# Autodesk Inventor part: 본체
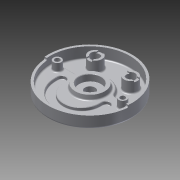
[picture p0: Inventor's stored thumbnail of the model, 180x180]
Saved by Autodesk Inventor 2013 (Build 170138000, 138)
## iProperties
Created: 2015-05
Part Number: 본체
Material: 알루미늄 6061
Document SubType Name: Modeling
Designer: Administrator
Density: 2.71 g/cm^3
Mass: 1085.43 g
Surface Area: 1039.14 cm^2
Volume: 400.527 cm^3
Author: Administrator
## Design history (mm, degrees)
sketch "스케치1"
  geometry: C1 r 95 at (0, 0); 1 further point
  constraints: 1 centre point, 1 coincident
  dimensions: "d0" = 190 diameter of C1
extrude "돌출1" new body sketch "스케치1" distance "d2" = 32; taper "d3" = 0 deg
sketch "스케치2"
  geometry: C1 r 95 at (0, 0) reference; C2 r 90 at (0, 0)
  constraints: 1 centre point, 1 coincident
  dimensions: "d4" = 180 diameter of C2
extrude "돌출2" cut sketch "스케치2" distance "d6" = 18; taper "d7" = 0 deg
sketch "스케치3"
  geometry: L1 (-89.196, 12)-(89.196, 12); L2 (-82.153, -19)-(80.893, -19); L3 (0, 0)-(0, -95); L4 (-82.153, -14)-(80.893, -14); L5 (59, -19)-(59, -14); L6 (41, -19)-(41, -14); L7 (-41, -19)-(-41, -14); L8 (-59, -19)-(-59, -14); A1 r 90 centre (0, 0) between (89.196, 12) and (-89.196, 12); A2 r 59 centre (0, -19) between (-59, -19) and (59, -19); A3 r 41 centre (0, -19) between (-41, -19) and (41, -19); A4 r 9 centre (50, -14) between (59, -14) and (41, -14); A5 r 9 centre (-50, -14) between (-41, -14) and (-59, -14); 3 further points
  constraints: 16 end point, 10 point on circle, 5 centre point, 5 point on line, 3 parallel, 3 symmetric about line, 3 tangent, 2 coincident, 2 perpendicular, 1 horizontal, 1 horizontal alignment, 1 midpoint, 1 vertical alignment, 2 other
  dimensions: "d10" = 90 radius of A1; "d11" = 12 distance from line of L1 point (0, 0); "d13" = 59 radius of A2; "d14" = 41 radius of A3; "d16" = 18 diameter of A4; "d17" = 5 distance of L8.start L8.end; "d18" = 5 distance of L7.start L7.end; "d130" = 19 distance from line of L2 L3.start; "d131" = 5 distance between parallel lines of L4 L2
extrude "돌출3" cut sketch "스케치3" distance "d19" = 7; taper "d20" = 0 deg
sketch "스케치4"
  geometry: L1 (89.196, 12)-(-89.196, 12) reference; A1 r 90 centre (0, 0) between (89.196, 12) and (-89.196, 12) reference; A2 r 42 centre (0, 0) between (40.249, 12) and (-40.249, 12)
  constraints: 2 point on circle, 2 point on line, 1 centre point, 1 coincident
  dimensions: "d21" = 84 diameter of A2
extrude "돌출4" join sketch "스케치4" distance "d23" = 7; taper "d24" = 0 deg
sketch "스케치5"
  geometry: C1 r 35 at (0, 0); A1 r 90 centre (0, 0) between (-89.196, 12) and (89.196, 12) reference
  constraints: 1 centre point, 1 coincident
  dimensions: "d25" = 70 diameter of C1
extrude "돌출5" join sketch "스케치5" distance "d26" = 10; taper "d27" = -10 deg
sketch "스케치6"
  geometry: C1 r 95 at (0, 0) reference; C2 r 25 at (0, 0)
  constraints: 1 centre point, 1 coincident
  dimensions: "d28" = 50 diameter of C2
extrude "돌출6" join sketch "스케치6" distance "d29" = 12; taper "d30" = -15 deg
hole "구멍1" diameter "d33" = 23; stored, may be unused: countersink angle "d37" = 90 deg, drill point angle "d39" = 0 deg; dims "d34" = 6, "d35" = 50, "d36" = 15, "d38" = 15, "d132" = 10, "d133" = 10
sketch "스케치7"
  geometry: L1 (-40.249, 12)-(-89.196, 12) reference; L2 (0, 90)-(0, 0); C1 r 15 at (-40, 52); C2 r 15 at (40, 52); A1 r 42 centre (0, 0) between (40.249, 12) and (-40.249, 12) reference; A2 r 90 centre (0, 0) between (89.196, 12) and (-89.196, 12) reference
  constraints: 2 centre point, 2 end point, 1 perpendicular, 1 point on circle, 1 symmetric about line, 1 other
  dimensions: "d42" = 30 diameter of C1; "d43" = 80 distance of C2.centre C1.centre; "d44" = 52 vertical distance of C2.centre A1.centre
extrude "돌출7" join sketch "스케치7" distance "d45" = 25; taper "d46" = 0 deg
hole "구멍2" diameter "d49" = 20; stored, may be unused: countersink angle "d53" = 90 deg, drill point angle "d55" = 0 deg; dims "d47" = 10, "d48" = 10, "d50" = 6, "d51" = 4, "d52" = 2, "d54" = 15
hole "구멍3" diameter "d58" = 20; stored, may be unused: countersink angle "d62" = 90 deg, drill point angle "d64" = 0 deg; dims "d56" = 10, "d57" = 10, "d59" = 6, "d60" = 4, "d61" = 2, "d63" = 15
sketch "스케치8"
  geometry: L1 (-6, 17.94)-(6, 17.94); L2 (6, 17.94)-(6, -17.94); L3 (6, -17.94)-(-6, -17.94); L4 (-6, -17.94)-(-6, 17.94); C1 r 10 at (0, 0) reference; 3 further points
  constraints: 8 end point, 2 midpoint, 2 parallel, 1 horizontal, 1 horizontal alignment, 1 perpendicular, 1 vertical alignment
  dimensions: "d65" = 12 distance between parallel lines of L2 L4; "d67" = 35.87996 distance between parallel lines of L3 L1
extrude "돌출8" cut sketch "스케치8" distance "d68" = 3; taper "d69" = 0 deg
sketch "스케치9"
  geometry: L1 (-18.483, 6)-(18.483, 6); L2 (18.483, 6)-(18.483, -6); L3 (18.483, -6)-(-18.483, -6); L4 (-18.483, -6)-(-18.483, 6); C1 r 10 at (0, 0) reference; 3 further points
  constraints: 8 end point, 2 midpoint, 2 parallel, 1 horizontal, 1 horizontal alignment, 1 perpendicular, 1 vertical alignment
  dimensions: "d70" = 12 distance between parallel lines of L3 L1; "d72" = 36.96686 distance between parallel lines of L2 L4
extrude "돌출9" cut sketch "스케치9" distance "d73" = 3; taper "d74" = 0 deg
sketch "스케치10"
  geometry: L1 (0, 0)-(0, -90); C1 r 35 at (0, 0) reference; C2 r 95 at (0, 0) reference; C3 r 9 at (-74, 0); C4 r 9 at (74, 0); A1 r 90 centre (0, 0) between (-89.196, 12) and (89.196, 12) reference
  constraints: 2 centre point, 2 end point, 1 horizontal alignment, 1 point on circle, 1 symmetric about line, 1 other
  dimensions: "d75" = 18 diameter of C3; "d76" = 148 distance of C4.centre C3.centre
extrude "돌출10" join sketch "스케치10" distance "d77" = 18; taper "d78" = 0 deg
sketch "스케치11"
  geometry: C1 r 9 at (-74, 0) reference; C2 r 9 at (74, 0) reference; C3 r 9 at (-74, 0) reference; 2 further points
  constraints: 2 coincident
hole "구멍4" sketch "스케치11" at (-74, 0), (74, 0) diameter "d79" = 11; stored, may be unused: countersink angle "d83" = 90 deg, drill point angle "d85" = 0 deg; dims "d80" = 6, "d81" = 18, "d82" = 11, "d84" = 15
sketch "스케치12"
  geometry: L1 (0, 0)-(-89.658, -7.844); L2 (0, 0)-(89.658, -7.844); L3 (-90, 0)-(90, 0); L4 (89.658, -7.844)-(94.638, -8.28); L5 (-89.658, -7.844)-(-94.638, -8.28); A1 r 90 centre (0, 0) between (-90, 0) and (89.196, 12) reference; A2 r 95 centre (0, 0) between (-94.638, -8.28) and (94.638, -8.28) reference; A3 r 90 centre (0, 0) between (-89.196, 12) and (89.196, 12) reference; A4 r 95 centre (0, 0) between (-94.638, -8.28) and (94.638, -8.28); A5 r 90 centre (0, 0) between (89.658, -7.844) and (-89.658, -7.844)
  constraints: 10 end point, 9 point on circle, 2 centre point, 2 coincident, 1 concentric, 1 horizontal, 1 midpoint
  dimensions: "d86" = 180 diameter of A5; "d88" = 5 deg angle of L1 L3; "d90" = 5 deg angle of L2 L3; "d92" = 5 deg angle of L5 L3; "d94" = 5 deg angle of L4 L3
extrude "돌출11" cut sketch "스케치12" distance "d96" = 5; taper "d97" = 0 deg
fillet "모깎기1" dims "d98" = 10
sketch "스케치13"
  geometry: L1 (0, 0)-(0, -72); L2 (0, 0)-(-36.062, -36.062); L3 (0, 0)-(36.062, -36.062); L4 (-36.062, -36.062)-(-50.912, -50.912); L5 (36.062, -36.062)-(50.912, -50.912); C1 r 25 at (0, 0) reference; C2 r 11.5 at (0, 0) reference; A1 r 51 centre (0, 0) between (-36.062, -36.062) and (36.062, -36.062); A2 r 72 centre (0, 0) between (71.48, -8.64) and (-50.912, -50.912); A3 r 72 centre (0, 0) between (50.912, -50.912) and (71.48, -8.64); A4 r 72 centre (0, 0) between (-50.912, -50.912) and (50.912, -50.912); A5 r 51 centre (0, 0) between (36.062, -36.062) and (-36.062, -36.062); 1 further point
  constraints: 12 point on circle, 10 end point, 5 centre point, 2 coincident, 1 symmetric about line, 1 vertical, 2 other
  dimensions: "d100" = 51 radius of A1; "d101" = 72 radius of A2; "d102" = 90 deg angle of L3 L2; "d103" = 21 distance of L3.end L5.end; "d105" = 14.84924 horizontal distance of L2.end L4.end
extrude "돌출12" join sketch "스케치13" distance "d106" = 5; taper "d107" = 0 deg
fillet "모깎기2" dims "d108" = 5
fillet "모깎기3" dims "d109" = 5
node "작업 평면1"
sketch "스케치16"
  geometry: L1 (-37.378, -41.502)-(-45.182, -49.306) reference; L2 (45.182, -49.306)-(37.378, -41.502) reference; A1 r 68 centre (0, 0) between (-45.74, -50.317) and (45.74, -50.317); 5 further points
  constraints: 2 horizontal alignment, 2 point on circle, 1 centre point, 1 coincident, 7 other
  dimensions: "d113" = 136 diameter of A1
feature "엠보싱1" sketch "스케치16" dims "d0" = 190, "d114" = 0.5, "d115" = 0
fillet "모깎기4" dims "d116" = 3
fillet "모깎기5" dims "d117" = 3
fillet "모깎기6" dims "d118" = 3
fillet "모깎기7" dims "d119" = 3
chamfer "모따기1" distance "d120" = 1; stored, may be unused: second distance "d121" = 2, angle "d122" = 45 deg
fillet "모깎기8" dims "d123" = 3
chamfer "모따기2" distance "d124" = 1; stored, may be unused: second distance "d125" = 2, angle "d126" = 45 deg
fillet "모깎기9" dims "d127" = 0.3
fillet "모깎기11" dims "d129" = 5
fillet "모깎기12" dims "d134" = 3
fillet "모깎기13" dims "d135" = 3
fillet "모깎기14" dims "d136" = 1
node "솔리드1"
node "투영된 루프1"
other parameters: "d112" = -139.25
